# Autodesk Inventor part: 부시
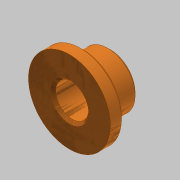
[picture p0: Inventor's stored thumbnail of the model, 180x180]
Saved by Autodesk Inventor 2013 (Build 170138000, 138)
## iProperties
Created: 2016-02
Part Number: 부시
Material: 스테인리스강
Document SubType Name: Modeling
Designer: mduedu
Density: 8.08 g/cm^3
Mass: 39.4553 g
Surface Area: 27.3717 cm^2
Volume: 4.88308 cm^3
Author: mduedu
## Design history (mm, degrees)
sketch "스케치1"
  geometry: C1 r 15 at (0, 0); 1 further point
  constraints: 1 centre point, 1 coincident
  dimensions: "d0" = 30 diameter of C1
extrude "돌출1" new body sketch "스케치1" distance "d1" = 5; taper "d2" = 0 deg
sketch "스케치2"
  geometry: C1 r 10 at (0, 0); 1 further point
  constraints: 1 centre point, 1 coincident
  dimensions: "d3" = 20 diameter of C1
extrude "돌출2" join sketch "스케치2" distance "d4" = 10; taper "d5" = 0 deg
hole "구멍1" diameter "d8" = 12; stored, may be unused: countersink angle "d12" = 90 deg, drill point angle "d14" = 118 deg; dims "d9" = 6, "d10" = 4, "d11" = 2, "d13" = 8, "d15" = 10, "d16" = 10
chamfer "모따기1" distance "d17" = 1; stored, may be unused: second distance "d18" = 2, angle "d19" = 45 deg
chamfer "모따기2" distance "d20" = 1; stored, may be unused: second distance "d21" = 2, angle "d22" = 45 deg
chamfer "모따기3" distance "d23" = 1; stored, may be unused: second distance "d24" = 2, angle "d25" = 45 deg
node "솔리드1"
